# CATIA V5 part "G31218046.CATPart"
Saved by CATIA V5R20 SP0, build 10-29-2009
Part number: G31218046
Revision: 7
Definition: design
Nomenclature: G31218046
Source: made
Description: NOT SPECIFIED
Bounding box of the stored display mesh (mm): x -8 to 46, y -15.5 to 15.5, z -15.5 to 15.5
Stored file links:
  C:\Users\Raffaele\Desktop\3D X SITO CF\BOLEX\23-BUSH REF 312\G31218046.CATPart

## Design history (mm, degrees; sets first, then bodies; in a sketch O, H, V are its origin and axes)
Body1 "MANIFOLD_SOLID_BREP #14651" (main body)
  Solid1: solid without history
Body2 "MANIFOLD_SOLID_BREP #14798"
  Solid2: solid without history
Body3 "MANIFOLD_SOLID_BREP #14945"
  Solid3: solid without history
Body4 "MANIFOLD_SOLID_BREP #15092"
  Solid4: solid without history
Body5 "MANIFOLD_SOLID_BREP #15239"
  Solid5: solid without history
Body6 "MANIFOLD_SOLID_BREP #15384"
  Solid6: solid without history
Body7 "MANIFOLD_SOLID_BREP #15529"
  Solid7: solid without history
Body8 "MANIFOLD_SOLID_BREP #15674"
  Solid8: solid without history
Body9 "MANIFOLD_SOLID_BREP #15819"
  Solid9: solid without history
Body10 "MANIFOLD_SOLID_BREP #15964"
  Solid10: solid without history
Body11 "MANIFOLD_SOLID_BREP #16109"
  Solid11: solid without history
Body12 "MANIFOLD_SOLID_BREP #16254"
  Solid12: solid without history
Body13 "MANIFOLD_SOLID_BREP #16399"
  Solid13: solid without history
Body14 "MANIFOLD_SOLID_BREP #16544"
  Solid14: solid without history
Body15 "MANIFOLD_SOLID_BREP #16689"
  Solid15: solid without history
Body16 "MANIFOLD_SOLID_BREP #16834"
  Solid16: solid without history
Body17 "MANIFOLD_SOLID_BREP #16979"
  Solid17: solid without history
Body18 "MANIFOLD_SOLID_BREP #17126"
  Solid18: solid without history
Body19 "MANIFOLD_SOLID_BREP #17273"
  Solid19: solid without history
Body20 "MANIFOLD_SOLID_BREP #17420"
  Solid20: solid without history
Body21 "MANIFOLD_SOLID_BREP #17567"
  Solid21: solid without history
Body22 "MANIFOLD_SOLID_BREP #17713"
  Solid22: solid without history
Body23 "MANIFOLD_SOLID_BREP #17860"
  Solid23: solid without history
Body24 "MANIFOLD_SOLID_BREP #18007"
  Solid24: solid without history
Body25 "MANIFOLD_SOLID_BREP #18153"
  Solid25: solid without history
Body26 "MANIFOLD_SOLID_BREP #18298"
  Solid26: solid without history
Body27 "MANIFOLD_SOLID_BREP #18443"
  Solid27: solid without history
Body28 "MANIFOLD_SOLID_BREP #18588"
  Solid28: solid without history
Body29 "MANIFOLD_SOLID_BREP #18733"
  Solid29: solid without history
Body30 "MANIFOLD_SOLID_BREP #18878"
  Solid30: solid without history
Body31 "MANIFOLD_SOLID_BREP #19023"
  Solid31: solid without history
Body32 "MANIFOLD_SOLID_BREP #19170"
  Solid32: solid without history
Body33 "MANIFOLD_SOLID_BREP #19317"
  Solid33: solid without history
Body34 "MANIFOLD_SOLID_BREP #19464"
  Solid34: solid without history
Body35 "MANIFOLD_SOLID_BREP #19611"
  Solid35: solid without history
Body36 "MANIFOLD_SOLID_BREP #19758"
  Solid36: solid without history
Body37 "MANIFOLD_SOLID_BREP #19905"
  Solid37: solid without history
Body38 "MANIFOLD_SOLID_BREP #20051"
  Solid38: solid without history
Body39 "MANIFOLD_SOLID_BREP #20198"
  Solid39: solid without history
Body40 "MANIFOLD_SOLID_BREP #20345"
  Solid40: solid without history
Body41 "MANIFOLD_SOLID_BREP #20491"
  Solid41: solid without history
Body42 "MANIFOLD_SOLID_BREP #20636"
  Solid42: solid without history
Body43 "MANIFOLD_SOLID_BREP #20781"
  Solid43: solid without history
Body44 "MANIFOLD_SOLID_BREP #20926"
  Solid44: solid without history
Body45 "MANIFOLD_SOLID_BREP #21071"
  Solid45: solid without history
Body46 "MANIFOLD_SOLID_BREP #21216"
  Solid46: solid without history
Body47 "MANIFOLD_SOLID_BREP #21361"
  Solid47: solid without history
Body48 "MANIFOLD_SOLID_BREP #21508"
  Solid48: solid without history
Body49 "MANIFOLD_SOLID_BREP #21655"
  Solid49: solid without history
Body50 "MANIFOLD_SOLID_BREP #21802"
  Solid50: solid without history
Body51 "MANIFOLD_SOLID_BREP #21949"
  Solid51: solid without history
Body52 "MANIFOLD_SOLID_BREP #22095"
  Solid52: solid without history
Body53 "MANIFOLD_SOLID_BREP #22242"
  Solid53: solid without history
Body54 "MANIFOLD_SOLID_BREP #22389"
  Solid54: solid without history
Body55 "MANIFOLD_SOLID_BREP #22535"
  Solid55: solid without history
Body56 "MANIFOLD_SOLID_BREP #22682"
  Solid56: solid without history
Body57 "MANIFOLD_SOLID_BREP #22829"
  Solid57: solid without history
Body58 "MANIFOLD_SOLID_BREP #22974"
  Solid58: solid without history
Body59 "MANIFOLD_SOLID_BREP #23119"
  Solid59: solid without history
Body60 "MANIFOLD_SOLID_BREP #23264"
  Solid60: solid without history
Body61 "MANIFOLD_SOLID_BREP #23409"
  Solid61: solid without history
Body62 "MANIFOLD_SOLID_BREP #23554"
  Solid62: solid without history
Body63 "MANIFOLD_SOLID_BREP #23699"
  Solid63: solid without history
Body64 "MANIFOLD_SOLID_BREP #23846"
  Solid64: solid without history
Body65 "MANIFOLD_SOLID_BREP #23993"
  Solid65: solid without history
Body66 "MANIFOLD_SOLID_BREP #24140"
  Solid66: solid without history
Body67 "MANIFOLD_SOLID_BREP #24287"
  Solid67: solid without history
Body68 "MANIFOLD_SOLID_BREP #24434"
  Solid68: solid without history
Body69 "MANIFOLD_SOLID_BREP #24581"
  Solid69: solid without history
Body70 "MANIFOLD_SOLID_BREP #24727"
  Solid70: solid without history
Body71 "MANIFOLD_SOLID_BREP #24874"
  Solid71: solid without history
Body72 "MANIFOLD_SOLID_BREP #25021"
  Solid72: solid without history
Body73 "MANIFOLD_SOLID_BREP #25167"
  Solid73: solid without history
Body74 "MANIFOLD_SOLID_BREP #25312"
  Solid74: solid without history
Body75 "MANIFOLD_SOLID_BREP #25457"
  Solid75: solid without history
Body76 "MANIFOLD_SOLID_BREP #25602"
  Solid76: solid without history
Body77 "MANIFOLD_SOLID_BREP #25747"
  Solid77: solid without history
Body78 "MANIFOLD_SOLID_BREP #25892"
  Solid78: solid without history
Body79 "MANIFOLD_SOLID_BREP #26037"
  Solid79: solid without history
Body80 "MANIFOLD_SOLID_BREP #26182"
  Solid80: solid without history
Body81 "MANIFOLD_SOLID_BREP #26327"
  Solid81: solid without history
Body82 "MANIFOLD_SOLID_BREP #26472"
  Solid82: solid without history
Body83 "MANIFOLD_SOLID_BREP #26617"
  Solid83: solid without history
Body84 "MANIFOLD_SOLID_BREP #26762"
  Solid84: solid without history
Body85 "MANIFOLD_SOLID_BREP #26907"
  Solid85: solid without history
Body86 "MANIFOLD_SOLID_BREP #27054"
  Solid86: solid without history
Body87 "MANIFOLD_SOLID_BREP #27201"
  Solid87: solid without history
Body88 "MANIFOLD_SOLID_BREP #27348"
  Solid88: solid without history
Body89 "MANIFOLD_SOLID_BREP #27495"
  Solid89: solid without history
Body90 "MANIFOLD_SOLID_BREP #27642"
  Solid90: solid without history
Body91 "MANIFOLD_SOLID_BREP #27789"
  Solid91: solid without history
Body92 "MANIFOLD_SOLID_BREP #27936"
  Solid92: solid without history
Body93 "MANIFOLD_SOLID_BREP #28083"
  Solid93: solid without history
Body94 "MANIFOLD_SOLID_BREP #28230"
  Solid94: solid without history
Body95 "MANIFOLD_SOLID_BREP #28377"
  Solid95: solid without history
Body96 "MANIFOLD_SOLID_BREP #28524"
  Solid96: solid without history
Body97 "MANIFOLD_SOLID_BREP #28671"
  Solid97: solid without history
Body98 "MANIFOLD_SOLID_BREP #28817"
  Solid98: solid without history
Body99 "MANIFOLD_SOLID_BREP #28963"
  Solid99: solid without history
Body100 "MANIFOLD_SOLID_BREP #29110"
  Solid100: solid without history
Body101 "MANIFOLD_SOLID_BREP #29257"
  Solid101: solid without history
Body102 "MANIFOLD_SOLID_BREP #29404"
  Solid102: solid without history
Body103 "MANIFOLD_SOLID_BREP #29551"
  Solid103: solid without history
Body104 "MANIFOLD_SOLID_BREP #29697"
  Solid104: solid without history
Body105 "MANIFOLD_SOLID_BREP #29843"
  Solid105: solid without history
